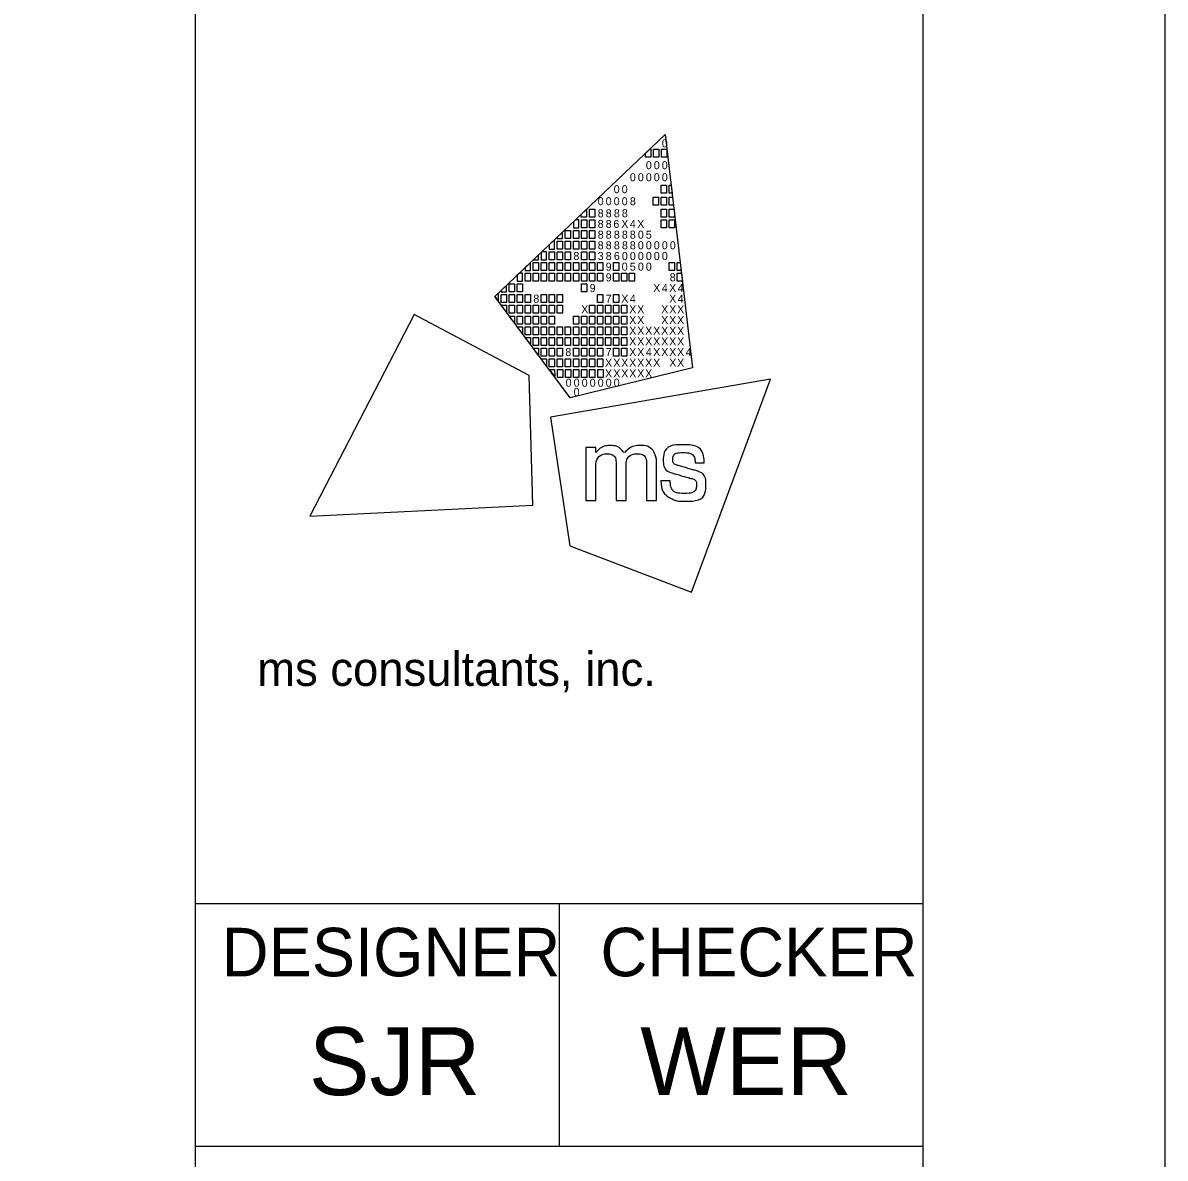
# Model space of a CAD drawing. Extents: x 0 to 34, y 0 to 22.
# Drawn here: x 31.644 to 34, y 2.475 to 4.816 of the extents above; entities that cross this region are included whole.
import ezdxf

# ---------------------------------------------------------------- set-up
doc = ezdxf.new("R2010")
doc.units = 0
for name, color, linetype in [('SH_Border', 7, 'Continuous'), ('SH_Cut_Line', 7, 'Continuous'), ('SH_Data', 7, 'Continuous'), ('SH_Text', 7, 'Continuous')]:
    doc.layers.add(name, color=color, linetype=linetype)

msp = doc.modelspace()

# ---------------------------------------------------------------- linework, layer by layer
at = {"layer": 'SH_Border'}
for p, q in [((32, 0.5), (32, 21.5)), ((32, 3), (33.5, 3)), ((32.75, 3), (32.75, 2.5)), ((32, 2.5), (33.5, 2.5))]:
    msp.add_line(p, q, dxfattribs=at)
msp.add_lwpolyline([(1.5, 21.5), (33.5, 21.5), (33.5, 0.5), (1.5, 0.5)], close=True, dxfattribs=at)
at = {"layer": 'SH_Cut_Line'}
msp.add_lwpolyline([(0, 0), (34, 0), (34, 22), (0, 22)], close=True, dxfattribs=at)
at = {"layer": 'SH_Data'}
msp.add_line((32.75, 4), (32.75, 4), dxfattribs=at)
at = {"layer": 'SH_Text'}
for p, q in [((32.6175, 4.2519), (32.9688, 4.5861)), ((32.9688, 4.5861), (32.9688, 4.5861)), ((32.9688, 4.5861), (33.0253, 4.1052)), ((32.773, 4.043), (32.6175, 4.2519)), ((33.0253, 4.1052), (32.773, 4.043))]:
    msp.add_line(p, q, dxfattribs=at)
for points in [[(32.9279, 4.5472), (32.9369, 4.5558), (32.9389, 4.5558), (32.9389, 4.5393), (32.9279, 4.5393)], [(32.9444, 4.5558), (32.9554, 4.5558), (32.9554, 4.5393), (32.9444, 4.5393)], [(32.9609, 4.5558), (32.9719, 4.5558), (32.9719, 4.5393), (32.9609, 4.5393)], [(32.9606, 4.4815), (32.9716, 4.4815), (32.9716, 4.465), (32.9606, 4.465)], [(32.9771, 4.4815), (32.9811, 4.4815), (32.983, 4.465), (32.9771, 4.465)], [(32.9441, 4.4567), (32.9551, 4.4567), (32.9551, 4.4402), (32.9441, 4.4402)], [(32.9606, 4.4567), (32.9716, 4.4567), (32.9716, 4.4402), (32.9606, 4.4402)], [(32.9771, 4.4567), (32.984, 4.4567), (32.9859, 4.4402), (32.9771, 4.4402)], [(32.7953, 4.4211), (32.8064, 4.4316), (32.8064, 4.4154), (32.7953, 4.4154)], [(32.8123, 4.4319), (32.8233, 4.4319), (32.8233, 4.4154), (32.8123, 4.4154)], [(32.9606, 4.4319), (32.9716, 4.4319), (32.9716, 4.4154), (32.9606, 4.4154)], [(32.9771, 4.4319), (32.9869, 4.4319), (32.9881, 4.4218), (32.9881, 4.4154), (32.9771, 4.4154)], [(32.7958, 4.4099), (32.8068, 4.4099), (32.8068, 4.3934), (32.7958, 4.3934)], [(32.8123, 4.4099), (32.8233, 4.4099), (32.8233, 4.3934), (32.8123, 4.3934)], [(32.9606, 4.4099), (32.9716, 4.4099), (32.9716, 4.3934), (32.9606, 4.3934)], [(32.9771, 4.4099), (32.9881, 4.4099), (32.9881, 4.3934), (32.9771, 4.3934)], [(32.7627, 4.3879), (32.7737, 4.3879), (32.7737, 4.3714), (32.7627, 4.3714)], [(32.7793, 4.3879), (32.7903, 4.3879), (32.7903, 4.3714), (32.7793, 4.3714)], [(32.7958, 4.3879), (32.8068, 4.3879), (32.8068, 4.3714), (32.7958, 4.3714)], [(32.8123, 4.3879), (32.8233, 4.3879), (32.8233, 4.3714), (32.8123, 4.3714)], [(32.7462, 4.3659), (32.7572, 4.3659), (32.7572, 4.3494), (32.7462, 4.3494)], [(32.7627, 4.3659), (32.7737, 4.3659), (32.7737, 4.3494), (32.7627, 4.3494)], [(32.7793, 4.3659), (32.7903, 4.3659), (32.7903, 4.3494), (32.7793, 4.3494)], [(32.7958, 4.3659), (32.8068, 4.3659), (32.8068, 4.3494), (32.7958, 4.3494)], [(32.8123, 4.3659), (32.8233, 4.3659), (32.8233, 4.3494), (32.8123, 4.3494)], [(32.7297, 4.3439), (32.7407, 4.3439), (32.7407, 4.3273), (32.7297, 4.3273)], [(32.7462, 4.3439), (32.7572, 4.3439), (32.7572, 4.3273), (32.7462, 4.3273)], [(32.7627, 4.3439), (32.7737, 4.3439), (32.7737, 4.3273), (32.7627, 4.3273)], [(32.7958, 4.3439), (32.8068, 4.3439), (32.8068, 4.3273), (32.7958, 4.3273)], [(32.8123, 4.3439), (32.8233, 4.3439), (32.8233, 4.3273), (32.8123, 4.3273)], [(32.6967, 4.3218), (32.7077, 4.3218), (32.7077, 4.3053), (32.6967, 4.3053)], [(32.7132, 4.3218), (32.7242, 4.3218), (32.7242, 4.3053), (32.7132, 4.3053)], [(32.7297, 4.3218), (32.7407, 4.3218), (32.7407, 4.3053), (32.7297, 4.3053)], [(32.7462, 4.3218), (32.7572, 4.3218), (32.7572, 4.3053), (32.7462, 4.3053)], [(32.7627, 4.3218), (32.7737, 4.3218), (32.7737, 4.3053), (32.7627, 4.3053)], [(32.7793, 4.3218), (32.7903, 4.3218), (32.7903, 4.3053), (32.7793, 4.3053)], [(32.7958, 4.3218), (32.8068, 4.3218), (32.8068, 4.3053), (32.7958, 4.3053)], [(32.8123, 4.3218), (32.8233, 4.3218), (32.8233, 4.3053), (32.8123, 4.3053)], [(32.8288, 4.3218), (32.8398, 4.3218), (32.8398, 4.3053), (32.8288, 4.3053)], [(32.8618, 4.3218), (32.8728, 4.3218), (32.8728, 4.3053), (32.8618, 4.3053)], [(32.9771, 4.3218), (32.9881, 4.3218), (32.9881, 4.3053), (32.9771, 4.3053)], [(32.9935, 4.3218), (32.9998, 4.3218), (33.0018, 4.3053), (32.9935, 4.3053)], [(32.6802, 4.2998), (32.6912, 4.2998), (32.6912, 4.2833), (32.6802, 4.2833)], [(32.6967, 4.2998), (32.7077, 4.2998), (32.7077, 4.2833), (32.6967, 4.2833)], [(32.7132, 4.2998), (32.7242, 4.2998), (32.7242, 4.2833), (32.7132, 4.2833)], [(32.7297, 4.2998), (32.7407, 4.2998), (32.7407, 4.2833), (32.7297, 4.2833)], [(32.7462, 4.2998), (32.7572, 4.2998), (32.7572, 4.2833), (32.7462, 4.2833)], [(32.7627, 4.2998), (32.7737, 4.2998), (32.7737, 4.2833), (32.7627, 4.2833)], [(32.7793, 4.2998), (32.7903, 4.2998), (32.7903, 4.2833), (32.7793, 4.2833)], [(32.7958, 4.2998), (32.8068, 4.2998), (32.8068, 4.2833), (32.7958, 4.2833)], [(32.8123, 4.2998), (32.8233, 4.2998), (32.8233, 4.2833), (32.8123, 4.2833)], [(32.8288, 4.2998), (32.8398, 4.2998), (32.8398, 4.2833), (32.8288, 4.2833)], [(32.8618, 4.2998), (32.8728, 4.2998), (32.8728, 4.2833), (32.8618, 4.2833)], [(32.8783, 4.2998), (32.8893, 4.2998), (32.8893, 4.2833), (32.8783, 4.2833)], [(32.8947, 4.2998), (32.9057, 4.2998), (32.9057, 4.2833), (32.8947, 4.2833)], [(32.9935, 4.2998), (33.0024, 4.2998), (33.0044, 4.2833), (32.9935, 4.2833)], [(32.6471, 4.2778), (32.6581, 4.2778), (32.6581, 4.2613), (32.6471, 4.2613)], [(32.6637, 4.2778), (32.6747, 4.2778), (32.6747, 4.2613), (32.6637, 4.2613)], [(32.7958, 4.2778), (32.8068, 4.2778), (32.8068, 4.2613), (32.7958, 4.2613)], [(32.6306, 4.2558), (32.6416, 4.2558), (32.6416, 4.2393), (32.6306, 4.2393)], [(32.6471, 4.2558), (32.6581, 4.2558), (32.6581, 4.2393), (32.6471, 4.2393)], [(32.6637, 4.2558), (32.6747, 4.2558), (32.6747, 4.2393), (32.6637, 4.2393)], [(32.6802, 4.2558), (32.6912, 4.2558), (32.6912, 4.2393), (32.6802, 4.2393)], [(32.7132, 4.2558), (32.7242, 4.2558), (32.7242, 4.2393), (32.7132, 4.2393)], [(32.7297, 4.2558), (32.7407, 4.2558), (32.7407, 4.2393), (32.7297, 4.2393)], [(32.7462, 4.2558), (32.7572, 4.2558), (32.7572, 4.2393), (32.7462, 4.2393)], [(32.8288, 4.2558), (32.8398, 4.2558), (32.8398, 4.2393), (32.8288, 4.2393)], [(32.8618, 4.2558), (32.8728, 4.2558), (32.8728, 4.2393), (32.8618, 4.2393)], [(32.6306, 4.2338), (32.6416, 4.2338), (32.6416, 4.22)], [(32.6471, 4.2338), (32.6581, 4.2338), (32.6581, 4.2173), (32.6471, 4.2173)], [(32.6637, 4.2338), (32.6747, 4.2338), (32.6747, 4.2173), (32.6637, 4.2173)], [(32.6802, 4.2338), (32.6912, 4.2338), (32.6912, 4.2173), (32.6802, 4.2173)], [(32.6967, 4.2338), (32.7077, 4.2338), (32.7077, 4.2173), (32.6967, 4.2173)], [(32.7132, 4.2338), (32.7242, 4.2338), (32.7242, 4.2173), (32.7132, 4.2173)], [(32.7297, 4.2338), (32.7407, 4.2338), (32.7407, 4.2173), (32.7297, 4.2173)], [(32.7462, 4.2338), (32.7572, 4.2338), (32.7572, 4.2173), (32.7462, 4.2173)], [(32.8123, 4.2338), (32.8233, 4.2338), (32.8233, 4.2173), (32.8123, 4.2173)], [(32.8288, 4.2338), (32.8398, 4.2338), (32.8398, 4.2173), (32.8288, 4.2173)], [(32.8453, 4.2338), (32.8563, 4.2338), (32.8563, 4.2173), (32.8453, 4.2173)], [(32.8618, 4.2338), (32.8728, 4.2338), (32.8728, 4.2173), (32.8618, 4.2173)], [(32.8783, 4.2338), (32.8893, 4.2338), (32.8893, 4.2173), (32.8783, 4.2173)], [(32.6471, 4.2117), (32.6581, 4.2117), (32.6581, 4.198)], [(32.6637, 4.2117), (32.6747, 4.2117), (32.6747, 4.1952), (32.6637, 4.1952)], [(32.6802, 4.2117), (32.6912, 4.2117), (32.6912, 4.1952), (32.6802, 4.1952)], [(32.6967, 4.2117), (32.7077, 4.2117), (32.7077, 4.1952), (32.6967, 4.1952)], [(32.7132, 4.2117), (32.7242, 4.2117), (32.7242, 4.1952), (32.7132, 4.1952)], [(32.7297, 4.2117), (32.7407, 4.2117), (32.7407, 4.1952), (32.7297, 4.1952)], [(32.7793, 4.2117), (32.7903, 4.2117), (32.7903, 4.1952), (32.7793, 4.1952)], [(32.7958, 4.2117), (32.8068, 4.2117), (32.8068, 4.1952), (32.7958, 4.1952)], [(32.8123, 4.2117), (32.8233, 4.2117), (32.8233, 4.1952), (32.8123, 4.1952)], [(32.8288, 4.2117), (32.8398, 4.2117), (32.8398, 4.1952), (32.8288, 4.1952)], [(32.8453, 4.2117), (32.8563, 4.2117), (32.8563, 4.1952), (32.8453, 4.1952)], [(32.8618, 4.2117), (32.8728, 4.2117), (32.8728, 4.1952), (32.8618, 4.1952)], [(32.8783, 4.2117), (32.8893, 4.2117), (32.8893, 4.1952), (32.8783, 4.1952)], [(32.6637, 4.1897), (32.6747, 4.1897), (32.6747, 4.176)], [(32.6747, 4.1897), (32.6747, 4.1897), (32.6747, 4.1897)], [(32.6802, 4.1897), (32.6912, 4.1897), (32.6912, 4.1732), (32.6802, 4.1732)], [(32.6967, 4.1897), (32.7077, 4.1897), (32.7077, 4.1732), (32.6967, 4.1732)], [(32.7132, 4.1897), (32.7242, 4.1897), (32.7242, 4.1732), (32.7132, 4.1732)], [(32.7297, 4.1897), (32.7407, 4.1897), (32.7407, 4.1732), (32.7297, 4.1732)], [(32.7462, 4.1897), (32.7572, 4.1897), (32.7572, 4.1732), (32.7462, 4.1732)], [(32.7627, 4.1897), (32.7737, 4.1897), (32.7737, 4.1732), (32.7627, 4.1732)], [(32.7793, 4.1897), (32.7903, 4.1897), (32.7903, 4.1732), (32.7793, 4.1732)], [(32.7958, 4.1897), (32.8068, 4.1897), (32.8068, 4.1732), (32.7958, 4.1732)], [(32.8123, 4.1897), (32.8233, 4.1897), (32.8233, 4.1732), (32.8123, 4.1732)], [(32.8288, 4.1897), (32.8398, 4.1897), (32.8398, 4.1732), (32.8288, 4.1732)], [(32.8453, 4.1897), (32.8563, 4.1897), (32.8563, 4.1732), (32.8453, 4.1732)], [(32.8618, 4.1897), (32.8728, 4.1897), (32.8728, 4.1732), (32.8618, 4.1732)], [(32.8783, 4.1897), (32.8893, 4.1897), (32.8893, 4.1732), (32.8783, 4.1732)], [(32.6802, 4.1677), (32.6912, 4.1677), (32.6912, 4.154)], [(32.6967, 4.1677), (32.7077, 4.1677), (32.7077, 4.1512), (32.6967, 4.1512)], [(32.7132, 4.1677), (32.7242, 4.1677), (32.7242, 4.1512), (32.7132, 4.1512)], [(32.7297, 4.1677), (32.7407, 4.1677), (32.7407, 4.1512), (32.7297, 4.1512)], [(32.7462, 4.1677), (32.7572, 4.1677), (32.7572, 4.1512), (32.7462, 4.1512)], [(32.7627, 4.1677), (32.7737, 4.1677), (32.7737, 4.1512), (32.7627, 4.1512)], [(32.7793, 4.1677), (32.7903, 4.1677), (32.7903, 4.1512), (32.7793, 4.1512)], [(32.7958, 4.1677), (32.8068, 4.1677), (32.8068, 4.1512), (32.7958, 4.1512)], [(32.8123, 4.1677), (32.8233, 4.1677), (32.8233, 4.1512), (32.8123, 4.1512)], [(32.8288, 4.1677), (32.8398, 4.1677), (32.8398, 4.1512), (32.8288, 4.1512)], [(32.8453, 4.1677), (32.8563, 4.1677), (32.8563, 4.1512), (32.8453, 4.1512)], [(32.8618, 4.1677), (32.8728, 4.1677), (32.8728, 4.1512), (32.8618, 4.1512)], [(32.8783, 4.1677), (32.8893, 4.1677), (32.8893, 4.1512), (32.8783, 4.1512)], [(32.7077, 4.1305), (32.6965, 4.1457), (32.7077, 4.1457)], [(32.7132, 4.1457), (32.7242, 4.1457), (32.7242, 4.1292), (32.7132, 4.1292)], [(32.724, 4.1082), (32.7132, 4.1237), (32.7242, 4.1237)], [(32.7297, 4.1457), (32.7407, 4.1457), (32.7407, 4.1292), (32.7297, 4.1292)], [(32.7297, 4.1237), (32.7407, 4.1237), (32.7407, 4.1072), (32.7297, 4.1072)], [(32.7462, 4.1457), (32.7572, 4.1457), (32.7572, 4.1292), (32.7462, 4.1292)], [(32.7462, 4.1237), (32.7572, 4.1237), (32.7572, 4.1072), (32.7462, 4.1072)], [(32.7627, 4.1237), (32.7737, 4.1237), (32.7737, 4.1072), (32.7627, 4.1072)], [(32.7793, 4.1457), (32.7903, 4.1457), (32.7903, 4.1292), (32.7793, 4.1292)], [(32.7793, 4.1237), (32.7903, 4.1237), (32.7903, 4.1072), (32.7793, 4.1072)], [(32.7958, 4.1457), (32.8068, 4.1457), (32.8068, 4.1292), (32.7958, 4.1292)], [(32.7958, 4.1237), (32.8068, 4.1237), (32.8068, 4.1072), (32.7958, 4.1072)], [(32.8123, 4.1457), (32.8233, 4.1457), (32.8233, 4.1292), (32.8123, 4.1292)], [(32.8123, 4.1237), (32.8233, 4.1237), (32.8233, 4.1072), (32.8123, 4.1072)], [(32.8288, 4.1457), (32.8398, 4.1457), (32.8398, 4.1292), (32.8288, 4.1292)], [(32.8288, 4.1237), (32.8398, 4.1237), (32.8398, 4.1072), (32.8288, 4.1072)], [(32.8618, 4.1457), (32.8728, 4.1457), (32.8728, 4.1292), (32.8618, 4.1292)], [(32.8783, 4.1457), (32.8893, 4.1457), (32.8893, 4.1292), (32.8783, 4.1292)], [(32.7302, 4.1017), (32.7407, 4.1017), (32.7408, 4.0875)], [(32.7463, 4.1017), (32.7573, 4.1017), (32.7573, 4.0852), (32.7463, 4.0852)], [(32.763, 4.1017), (32.774, 4.1017), (32.774, 4.0852), (32.763, 4.0852)], [(32.7794, 4.1017), (32.7904, 4.1017), (32.7904, 4.0852), (32.7794, 4.0852)], [(32.796, 4.1017), (32.807, 4.1017), (32.807, 4.0852), (32.796, 4.0852)], [(32.8129, 4.1017), (32.8239, 4.1017), (32.8239, 4.0851), (32.8129, 4.0851)], [(32.8296, 4.1017), (32.8406, 4.1017), (32.8406, 4.0851), (32.8296, 4.0851)]]:
    msp.add_lwpolyline(points, close=True, dxfattribs=at)
for points in [[(32.7903, 4.4099), (32.7836, 4.4099), (32.7793, 4.4058), (32.7793, 4.3934), (32.7903, 4.3934), (32.7903, 4.4099)], [(32.7572, 4.3849), (32.7462, 4.3744), (32.7462, 4.3714), (32.7572, 4.3714), (32.7572, 4.3849)], [(32.7407, 4.3691), (32.7297, 4.3587), (32.7297, 4.3494), (32.7407, 4.3494), (32.7407, 4.3691)], [(32.7077, 4.3377), (32.6968, 4.3273), (32.7077, 4.3273), (32.7077, 4.3377)], [(32.7242, 4.3439), (32.7141, 4.3439), (32.7132, 4.343), (32.7132, 4.3273), (32.7242, 4.3273), (32.7242, 4.3439)], [(32.6912, 4.322), (32.6802, 4.3115), (32.6802, 4.3053), (32.6912, 4.3053), (32.6912, 4.322)], [(32.6747, 4.2998), (32.6679, 4.2998), (32.6637, 4.2958), (32.6637, 4.2833), (32.6747, 4.2833), (32.6747, 4.2998)], [(32.6416, 4.2749), (32.6306, 4.2644), (32.6306, 4.2613), (32.6416, 4.2613), (32.6416, 4.2749)], [(32.6251, 4.2558), (32.6216, 4.2558), (32.6175, 4.2519), (32.6251, 4.2417), (32.6251, 4.2558)], [(32.4512, 4.2149), (32.2359, 3.7988), (32.6956, 3.8215), (32.6884, 4.0892), (32.4512, 4.2149)], [(33.0229, 3.6422), (33.1859, 4.0814), (32.7324, 4.0029), (32.7722, 3.7381), (33.0229, 3.6422)]]:
    msp.add_lwpolyline(points, dxfattribs=at)
for points in [[(32.8048, 3.8315), (32.8048, 3.8315), (32.8048, 3.9409), (32.8048, 3.9409), (32.8048, 3.9409), (32.8255, 3.9409), (32.8255, 3.9409), (32.8255, 3.9409), (32.8255, 3.9297), (32.8255, 3.9297), (32.8346, 3.9399), (32.8457, 3.9445), (32.8555, 3.9445), (32.8688, 3.9445), (32.8791, 3.9372), (32.8837, 3.9266), (32.8915, 3.9381), (32.905, 3.9446), (32.9166, 3.9446), (32.9325, 3.9446), (32.9451, 3.935), (32.9494, 3.9213), (32.9494, 3.9212), (32.9494, 3.9212), (32.9494, 3.9212), (32.9501, 3.919), (32.9506, 3.9172), (32.9506, 3.9071), (32.9506, 3.9071), (32.9506, 3.8314), (32.9506, 3.8314), (32.9506, 3.8314), (32.9303, 3.8314), (32.9303, 3.8314), (32.9303, 3.8314), (32.9303, 3.9048), (32.9303, 3.9048), (32.9303, 3.9201), (32.9219, 3.9274), (32.911, 3.9274), (32.8995, 3.9274), (32.8879, 3.9171), (32.8879, 3.9001), (32.8879, 3.9001), (32.8879, 3.8315), (32.8879, 3.8315), (32.8879, 3.8315), (32.8674, 3.8315), (32.8674, 3.8315), (32.8674, 3.8315), (32.8674, 3.9059), (32.8674, 3.9059), (32.8674, 3.9203), (32.8588, 3.9274), (32.8496, 3.9274), (32.8384, 3.9274), (32.8254, 3.917), (32.8254, 3.8962), (32.8254, 3.8962), (32.8254, 3.8315), (32.8254, 3.8315), (32.8254, 3.8315), (32.8048, 3.8315), (32.8048, 3.8315)], [(32.9595, 3.8709), (32.9595, 3.8709), (32.9595, 3.8717), (32.9595, 3.8717), (32.9595, 3.8717), (32.9603, 3.8717), (32.9603, 3.8717), (32.9603, 3.8717), (32.9783, 3.8717), (32.9783, 3.8717), (32.9783, 3.8717), (32.9789, 3.8717), (32.9789, 3.8717), (32.9789, 3.8717), (32.979, 3.871), (32.979, 3.871), (32.9803, 3.8554), (32.9887, 3.846), (33.009, 3.846), (33.0273, 3.846), (33.0333, 3.8554), (33.0333, 3.8631), (33.0333, 3.8732), (33.0256, 3.8758), (33.0175, 3.878), (33.0175, 3.878), (32.987, 3.8867), (32.987, 3.8867), (32.972, 3.8909), (32.9648, 3.9019), (32.9648, 3.9142), (32.9648, 3.9303), (32.9768, 3.9462), (33.0052, 3.9462), (33.0348, 3.9462), (33.0489, 3.9285), (33.0489, 3.9095), (33.0489, 3.9095), (33.0489, 3.9087), (33.0489, 3.9087), (33.0489, 3.9087), (33.0482, 3.9087), (33.0482, 3.9087), (33.0482, 3.9087), (33.0312, 3.9087), (33.0312, 3.9087), (33.0312, 3.9087), (33.0305, 3.9087), (33.0305, 3.9087), (33.0305, 3.9087), (33.0305, 3.9094), (33.0305, 3.9094), (33.0301, 3.9208), (33.0226, 3.93), (33.0056, 3.93), (32.9891, 3.93), (32.9843, 3.9218), (32.9843, 3.9157), (32.9843, 3.9108), (32.9869, 3.9059), (32.9959, 3.9033), (32.9959, 3.9033), (33.0255, 3.8948), (33.0255, 3.8948), (33.0462, 3.8889), (33.0527, 3.8777), (33.0527, 3.8639), (33.0527, 3.8462), (33.041, 3.8298), (33.0087, 3.8298), (32.9952, 3.8298), (32.9877, 3.8321), (32.9823, 3.8348), (32.969, 3.8414), (32.9609, 3.8536), (32.9595, 3.8709)]]:
    msp.add_open_spline(points, degree=3, dxfattribs=at)

# ---------------------------------------------------------------- texts
at = {"layer": 'SH_Border'}
msp.add_text('ms consultants, inc.', height=0.07, rotation=360, dxfattribs=at).set_placement((32.1273, 3.4489))
at = {"layer": 'SH_Data'}
for s, height, p in [('DESIGNER', 0.1, (32.054, 2.85)), ('CHECKER', 0.1, (32.8352, 2.85)), ('SJR', 0.14, (32.2339, 2.605)), ('WER', 0.14, (32.9173, 2.605))]:
    msp.add_text(s, height=height, dxfattribs=at).set_placement(p)
at = {"layer": 'SH_Text'}
for s, p in [('0', (32.9617, 4.5597)), ('0', (32.9288, 4.5145)), ('0', (32.9452, 4.5145)), ('0', (32.9617, 4.5145)), ('0', (32.8958, 4.4897)), ('0', (32.9123, 4.4897)), ('0', (32.9288, 4.4897)), ('0', (32.9452, 4.4897)), ('0', (32.9617, 4.4897)), ('0', (32.8625, 4.465)), ('0', (32.879, 4.465)), ('0', (32.8295, 4.4402)), ('0', (32.846, 4.4402)), ('0', (32.8625, 4.4402)), ('0', (32.879, 4.4402)), ('8', (32.8958, 4.4402)), ('8', (32.8295, 4.4154)), ('8', (32.846, 4.4154)), ('8', (32.8628, 4.4154)), ('8', (32.8793, 4.4154)), ('8', (32.8295, 4.3934)), ('8', (32.846, 4.3934)), ('6', (32.8618, 4.3934)), ('X', (32.8781, 4.3934)), ('4', (32.8958, 4.3934)), ('X', (32.911, 4.3934)), ('8', (32.8295, 4.3713)), ('8', (32.846, 4.3713)), ('8', (32.8628, 4.3713)), ('8', (32.8794, 4.3713)), ('8', (32.8958, 4.3713)), ('0', (32.9123, 4.3713)), ('5', (32.9287, 4.3713)), ('8', (32.8295, 4.3494)), ('8', (32.846, 4.3494)), ('8', (32.8628, 4.3494)), ('8', (32.8794, 4.3494)), ('8', (32.8958, 4.3494)), ('0', (32.9123, 4.3494)), ('0', (32.9288, 4.3494)), ('0', (32.9452, 4.3494)), ('0', (32.9617, 4.3494)), ('0', (32.9782, 4.3494)), ('8', (32.7793, 4.3273)), ('3', (32.8295, 4.3273)), ('8', (32.846, 4.3273)), ('6', (32.8629, 4.3273)), ('0', (32.8793, 4.3273)), ('0', (32.8958, 4.3273)), ('0', (32.9123, 4.3273)), ('0', (32.9288, 4.3273)), ('0', (32.9452, 4.3273)), ('0', (32.9617, 4.3273)), ('9', (32.846, 4.3053)), ('0', (32.879, 4.3053)), ('5', (32.8957, 4.3053)), ('0', (32.9123, 4.3053)), ('0', (32.9288, 4.3053)), ('9', (32.846, 4.2833)), ('8', (32.9781, 4.2833)), ('9', (32.813, 4.2613)), ('X', (32.9439, 4.2613)), ('4', (32.9617, 4.2613)), ('X', (32.9769, 4.2613)), ('4', (32.9946, 4.2613)), ('8', (32.6967, 4.2393)), ('7', (32.846, 4.2393)), ('X', (32.8781, 4.2393)), ('4', (32.8958, 4.2393)), ('X', (32.9769, 4.2393)), ('4', (32.9946, 4.2393)), ('X', (32.7955, 4.2173)), ('X', (32.8945, 4.2173)), ('X', (32.911, 4.2173)), ('X', (32.9604, 4.2173)), ('X', (32.9769, 4.2173)), ('X', (32.9933, 4.2173)), ('X', (32.8945, 4.1952)), ('X', (32.911, 4.1952)), ('X', (32.9604, 4.1952)), ('X', (32.9769, 4.1952)), ('X', (32.9933, 4.1952)), ('X', (32.8945, 4.1732)), ('X', (32.911, 4.1732)), ('X', (32.9274, 4.1732)), ('X', (32.9439, 4.1732)), ('X', (32.9604, 4.1732)), ('X', (32.9769, 4.1732)), ('X', (32.9933, 4.1732)), ('X', (32.8945, 4.1512)), ('X', (32.911, 4.1512)), ('X', (32.9274, 4.1512)), ('X', (32.9439, 4.1512)), ('X', (32.9604, 4.1512)), ('X', (32.9769, 4.1512)), ('X', (32.9933, 4.1512)), ('8', (32.7627, 4.1292)), ('X', (32.8447, 4.1072)), ('7', (32.846, 4.1292)), ('X', (32.8616, 4.1072)), ('X', (32.878, 4.1072)), ('X', (32.8945, 4.1292)), ('X', (32.8945, 4.1072)), ('X', (32.911, 4.1292)), ('X', (32.911, 4.1072)), ('X', (32.9274, 4.1072)), ('4', (32.9288, 4.1292)), ('X', (32.9439, 4.1292)), ('X', (32.9439, 4.1072)), ('X', (32.9604, 4.1292)), ('X', (32.9769, 4.1292)), ('X', (32.9771, 4.1072)), ('X', (32.9933, 4.1292)), ('X', (32.9933, 4.1072)), ('4', (33.0111, 4.1292)), ('X', (32.8447, 4.0851)), ('X', (32.8616, 4.0851)), ('X', (32.878, 4.0851)), ('X', (32.8945, 4.0851)), ('X', (32.911, 4.0851)), ('X', (32.9274, 4.0851)), ('0', (32.7634, 4.0659)), ('0', (32.7799, 4.0659)), ('0', (32.7965, 4.0659)), ('0', (32.813, 4.0659)), ('0', (32.8295, 4.0659)), ('0', (32.846, 4.0659)), ('0', (32.8625, 4.0659)), ('0', (32.7799, 4.0467))]:
    msp.add_text(s, height=0.0165, rotation=360, dxfattribs=at).set_placement(p)

doc.saveas('drawing.dxf')
